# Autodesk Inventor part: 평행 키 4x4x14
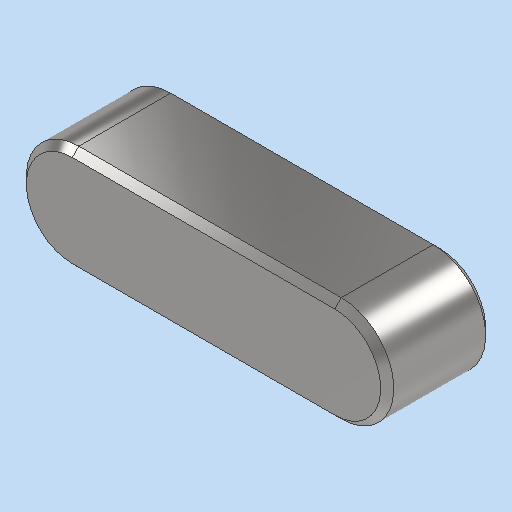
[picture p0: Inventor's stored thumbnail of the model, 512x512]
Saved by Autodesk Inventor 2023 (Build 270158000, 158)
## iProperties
Created: 2024-12
Part Number: 평행 키 4x4x14
Material: 강철, 연강
Description: 키 및 해당 키홈
Document SubType Name: Modeling
Designer: asung
Density: 7.85 g/cm^3
Appearance: 기본값
Author: jhkim
Sending System: Autodesk Inventor 2025
Preprocessor: ST-DEVELOPER v20
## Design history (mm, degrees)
feature "Solid1"
node "솔리드1"
